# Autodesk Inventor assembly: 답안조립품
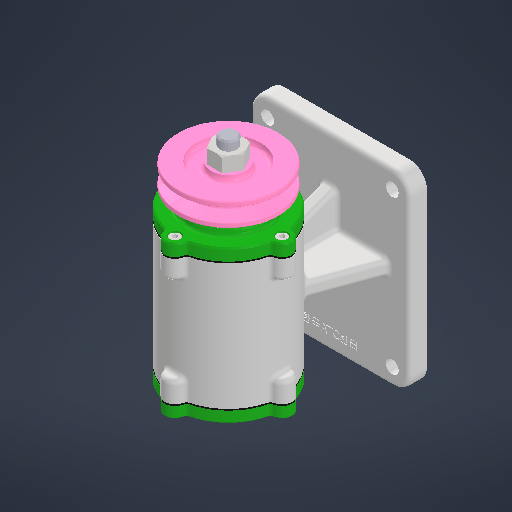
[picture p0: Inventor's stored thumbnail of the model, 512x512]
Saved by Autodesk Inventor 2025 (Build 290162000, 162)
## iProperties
Created: 2025-08
Part Number: 답안조립품
Document SubType Name: Assembly
Designer: infra14
Author: infra14
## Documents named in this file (12)
- C:\Users\infra14\Desktop\최준용\답안조립품.iam
- C:\Users\infra14\Desktop\최준용\본체.ipt
- C:\Users\infra14\Desktop\최준용\V-벨트풀리.ipt
- C:\Users\infra14\Desktop\최준용\개스킷.ipt
- C:\Users\infra14\Desktop\최준용\너트 M12 x 1.25.ipt
- C:\Users\infra14\Desktop\최준용\뒤커버.ipt
- C:\Users\infra14\Desktop\최준용\베어링 6204.ipt
- C:\Users\infra14\Desktop\최준용\볼트 M4 x 12.ipt
- C:\Users\infra14\Desktop\최준용\앞커버.ipt
- C:\Users\infra14\Desktop\최준용\오일 실.ipt
- C:\Users\infra14\Desktop\최준용\축.ipt
- C:\Users\infra14\Desktop\최준용\키 4 x 4.ipt
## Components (3 placed, 2 different names)
1. V-벨트풀리:1
2. 개스킷:1
3. 개스킷:2
